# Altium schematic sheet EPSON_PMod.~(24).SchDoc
size A4
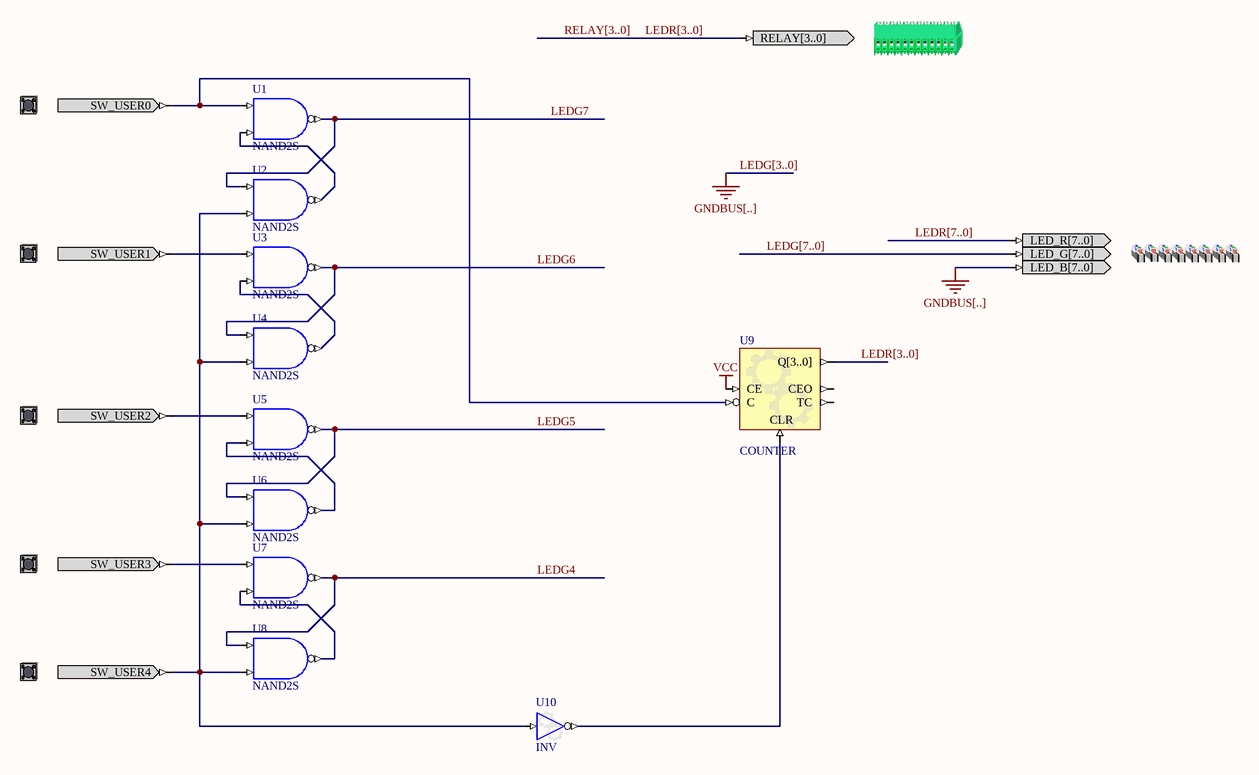
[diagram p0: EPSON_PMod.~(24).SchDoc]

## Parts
(Parts that share a designator on the sheet are numbered #1, #2 ... from top to bottom, then left to right.)
?#1  RELAYCNTR  (value not drawn)
?#2  USER_BUTTON0  (value not drawn)
?#3  LEDS_RGB  (value not drawn)
?#4  USER_BUTTON1  (value not drawn)
?#5  USER_BUTTON2  (value not drawn)
?#6  USER_BUTTON3  (value not drawn)
?#7  USER_BUTTON4  (value not drawn)
U1  NAND2S
U2  NAND2S
U3  NAND2S
U4  NAND2S
U5  NAND2S
U6  NAND2S
U7  NAND2S
U8  NAND2S
U9  COUNTER
U10  INV

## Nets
VCC: U9.CE
LEDG4: U7.O U8.I0
LEDG5: U5.O U6.I0
LEDG6: U3.O U4.I0
LEDG7: U1.O U2.I0
Net?#2_SW_USER0: ?#2.SW_USER0 U1.I0 U9.C
Net?#4_SW_USER1: ?#4.SW_USER1 U3.I0
Net?#5_SW_USER2: ?#5.SW_USER2 U5.I0
Net?#6_SW_USER3: ?#6.SW_USER3 U7.I0
Net?#7_SW_USER4: ?#7.SW_USER4 U2.I1 U4.I1 U6.I1 U8.I1 U10.I
NetU1_I1: U1.I1 U2.O
NetU3_I1: U3.I1 U4.O
NetU5_I1: U5.I1 U6.O
NetU7_I1: U7.I1 U8.O
NetU9_CLR: U9.CLR U10.O

Not connected (* = marked no-connect by the designer): ?#1 RELAY[3..0]; ?#3 LED_B[7..0] LED_G[7..0] LED_R[7..0]; U9 CEO Q[3..0] TC

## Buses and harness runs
bus LEDG[3..0]
bus LEDG[7..0]
bus LEDR[3..0]
bus LEDR[3..0] = RELAY[3..0]
bus LEDR[7..0]

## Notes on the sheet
- Labels drawn without touching a wire or pin: GNDBUS[..]

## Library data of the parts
?#1 = RELAYCNTR: RELAY; PortComponent: True
?#2 = USER_BUTTON0: Generic User Button; PortComponent: True
?#3 = LEDS_RGB: LEDS RGB; PortComponent: True
?#4 = USER_BUTTON1: Generic User Button; PortComponent: True
?#5 = USER_BUTTON2: Generic User Button; PortComponent: True
?#6 = USER_BUTTON3: Generic User Button; PortComponent: True
?#7 = USER_BUTTON4: Generic User Button; PortComponent: True
U1-U8 = NAND2S: 2-Input NAND Gate, Single Pin Version; XilinxEquivalent: NAND2; FunctionalClass: Logic Primitive; PortSize: 2; ArchiveName: GENERIC; VHDLIB_SIM: GENERIC_LIB
U9 = COUNTER: Configurable Counter; ConfiguratorName: GENERIC_COUNTER; ConfigurationParameters: {}Version[1.0]{}Type[Binary]{}SyncReset[False]{}NegativeClockEdge[True]{}FixedDirection[True]{}IsIncrement[True]{}SignalWidth[4]{}MaxValue[15]{}BusOutput[True]{}Loadable[False]{}BusInput[False]{}
U10 = INV: Configurable Inverter; ConfigurationParameters: {}Version[1.1]{}SignalCount[1]{}SignalWidth0[1]{}OutputOption0[Inverted]{}EnableMode[None]{}ShowPinNames[False]{}; ConfiguratorName: GENERIC_BUFFER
